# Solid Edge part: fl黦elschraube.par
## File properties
Title: Flügelschraube M8
Subject: Schmiege
Author: rauh
Template: Normal.par
Last saved by: ra-tv
Revision: 3
Application: Solid Edge
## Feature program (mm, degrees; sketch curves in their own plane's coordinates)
sketch for "unnamed RevolvedProtrusion 1" plane through (0, 0, 0) normal (0, 0, 1) x-axis (1, 0, 0)
  line (0, 0) -> (6, 0)
  line (3, 10) -> (6, 0)
  line (0, 10) -> (3, 10)
revolve "unnamed RevolvedProtrusion 1" add finite 360 deg about sketch line (0, 0) -> (0, 10)
sketch for "unnamed Protrusion 1" plane through (0, 0, 0) normal (0, -1, 0) x-axis (0, 0, -1)
  circle centre (0, 0) radius 4
extrude "unnamed Protrusion 1" add finite 18 along +normal
thread "unnamed Thread 1"
sketch for "unnamed Protrusion 2" plane through (0, 0, 0) normal (0, 0, 1) x-axis (1, 0, 0)
  line (3.4946, 8.3513) -> (11.2735, 15.72)
  line (5.1993, 2.6689) -> (15.4869, 8.0656)
extrude "unnamed Protrusion 2" add finite 2 symmetric
mirror "unnamed Mirror 1" of "unnamed Protrusion 2"
pattern "unnamed Pattern 1"
